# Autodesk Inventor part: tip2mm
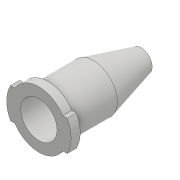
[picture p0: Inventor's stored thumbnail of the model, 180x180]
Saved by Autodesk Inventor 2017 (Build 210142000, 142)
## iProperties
Created: 2018-10
Part Number: tip2mm
Material: Generic
Document SubType Name: Modeling
Designer: JK
Density: 1 g/cm^3
Appearance: Default
Author: JK
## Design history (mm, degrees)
sketch "Sketch1"
  geometry: C1 r 2.8 at (0, 0); 1 further point
  constraints: 1 centre point
  dimensions: "d1" = 5.6 diameter of C1
extrude "Extrusion1" new body sketch "Sketch1" distance "d2" = 12; taper "d3" = 0 deg
sketch "Sketch2"
  geometry: C1 r 2.135 at (0, 0); 1 further point
  constraints: 1 centre point, 1 coincident
  dimensions: "d4" = 4.27 diameter of C1
extrude "Extrusion2" cut sketch "Sketch2" distance "d5" = 3.5; taper "d6" = 0 deg
sketch "Sketch3"
  geometry: C1 r 2.135 at (0, 0); 1 further point
  constraints: 1 centre point, 1 coincident
extrude "Extrusion3" cut sketch "Sketch3" distance "d7" = 5; taper "d8" = -5 deg
sketch "Sketch5"
  geometry: L1 (3.78, -1.8)-(-3.78, 1.8); L2 (-3.78, -1.8)-(3.78, 1.8); L3 (-3.78, 1.8)-(-2.808, 1.8); L4 (2.808, 1.8)-(3.324, 1.8); L5 (3.324, -1.8)-(2.808, -1.8); L6 (-2.808, -1.8)-(-3.324, -1.8); C1 r 2.8 at (0, 0) reference; A1 r 3.78 centre (0, 0) between (3.324, -1.8) and (3.324, 1.8); A2 r 3.78 centre (0, 0) between (-3.324, 1.8) and (-3.324, -1.8); A3 r 3.335 centre (0, 0) between (-2.808, -1.8) and (2.808, -1.8); A4 r 3.335 centre (0, 0) between (2.808, 1.8) and (-2.808, 1.8)
  constraints: 12 end point, 8 point on circle, 4 centre point, 4 parallel, 2 horizontal, 2 midpoint, 1 coincident, 1 point on line
  dimensions: "d30" = 7.56 distance of L1.end L2.end; "d31" = 3.6 distance of L2.start L1.end
extrude "Extrusion6" join sketch "Sketch5" distance "d32" = 1.07; taper "d33" = 0 deg
sketch "Sketch6"
  geometry: C1 r 1 at (0, 0); 1 further point
  constraints: 1 centre point, 1 coincident
  dimensions: "d34" = 2 diameter of C1
extrude "Extrusion7" cut sketch "Sketch6" stored distance "d35" = 7.18; taper "d36" = 11 deg
chamfer "Chamfer4" distance "d37" = 1.5; stored, may be unused: second distance "d38" = 2, angle "d39" = 75 deg
body "Solid1"
other parameters: "d28" = 6.67, "d29" = 7.56
